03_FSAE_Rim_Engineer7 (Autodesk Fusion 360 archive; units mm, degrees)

design "03 FSAE Rim - Engineer 7" references "Hexagon Socket Head Cap Screw DIN 912 - M4 x 0.7 x 16 Steel 4.6 Plain", "Hexagon Nut DIN 934 - M4 x 0.7 Steel 6 Plain"
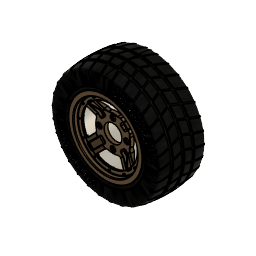
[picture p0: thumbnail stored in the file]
part number: 2026-07-27-09-56-27-671
part number: 2026-08-04-10-59-52-273
part number: 2026-08-04-10-59-52-284
part number: 2026-08-04-10-59-52-289
sketch "Sketch1" plane through (0, 0, 0) normal (1, 0, 0) x axis (0, 1, 0)
  line L1 (153.5, 0) -> (0, 0)
  line L2 (0, 119.5) -> (0, 104)
  line L3 (143.5, 124.5) -> (5, 124.5)
  line L4 (148.5, 134.75) -> (148.5, 129.5)
  line L5 (153.5, 138.25) -> (152, 138.25)
  line L6 (2.5, 119.5) -> (2.5, 104)
  line L7 (143.5, 122) -> (5, 122)
  line L8 (151, 134.75) -> (151, 129.5)
  line L9 (153.5, 135.75) -> (152, 135.75)
  line L10 (2.5, 104) -> (0, 104)
  line L11 (153.5, 135.75) -> (153.5, 138.25)
  arc A1 centre (152, 134.75) radius 3.5 clockwise from (148.5, 134.75) to (152, 138.25)
  arc A2 centre (143.5, 129.5) radius 5 clockwise from (148.5, 129.5) to (143.5, 124.5)
  arc A3 centre (5, 119.5) radius 5 clockwise from (0, 119.5) to (5, 124.5)
  arc A4 centre (5, 119.5) radius 2.5 clockwise from (2.5, 119.5) to (5, 122)
  arc A5 centre (143.5, 129.5) radius 7.5 clockwise from (151, 129.5) to (143.5, 122)
  arc A6 centre (152, 134.75) radius 1 clockwise from (151, 134.75) to (152, 135.75)
  point P1 (0, 0)
  point P2 (0, 0)
  point P4 (0, 104)
  point P3 (153.5, 0)
  point P7 (153.5, 138.25)
  point P6 (148.5, 124.5)
  point P5 (0, 124.5)
  coincident P1 P2
  horizontal L1
  perpendicular L1 L2
  perpendicular L2 L3
  perpendicular L3 L4
  perpendicular L4 L5
  vertical P1 P4
  vertical P3 P7
  tangent L4 A1
  tangent L5 A1
  coincident P6 L3
  coincident P6 L4
  tangent L3 A2
  tangent L4 A2
  coincident P5 L2
  coincident P5 L3
  tangent L2 A3
  tangent L3 A3
  equal A2 A3
  perpendicular L6 L10
  perpendicular L9 L11
  dimension "d1" distance P2 P3 = 153.5
  dimension "d2" = 208
  dimension "d3" = 249
  dimension "d4" = 276.5
  dimension "d5" distance P5 P6 = 148.5
  dimension "d6" radius A1 = 3.5
  dimension "d7" radius A2 = 5
  dimension "d8" = 2.5
revolve "Revolve1" sketch "Sketch1" AlongAngle 360 bodies "FSAE Rim Back"
sketch "Sketch2" plane through (0, 0, 0) normal (0, -1, 0) x axis (1, 0, 0)
  circle C1 centre (0, 0) radius 104
  circle C2 centre (0, 0) radius 119.5
  circle C3 centre (0, 0) radius 112
  circle C4 centre (0, 112) radius 2.15
  point P1 (0, 0)
  point P3 (0, 0)
  point P4 (0, 112)
  coincident P1 P3
  coincident C3 P4
  vertical P3 P4
  dimension "d10" diameter C3 = 224
  dimension "d11" diameter C4 = 4.3
extrude "Extrude1" cut sketch "Sketch2" profile of C4 to an object
circular_pattern "C-Pattern1" TotalAngle 360
canvas "Canvas1"
move "Move1"
sketch "Sketch4" plane through (0, 0, 0) normal (1, 0, 0) x axis (0, 1, 0)
  line L1 (14, 0) -> (0, 0)
  line L2 (14, 72.5) -> (14, 0)
  line L3 (-8, 102.5) -> (14, 72.5)
  line L4 (-8, 124.5) -> (-8, 102.5)
  line L5 (-23.5, 124.5) -> (-8, 124.5)
  line L6 (-23.5, 138) -> (-23.5, 124.5)
  line L7 (-28.25, 138) -> (-23.5, 138)
  line L8 (-28.25, 0) -> (-28.25, 138)
  line L9 (0, 0) -> (-28.25, 0)
  line L10 (-13, 118.1658) -> (-28.25, 119.5)
  line L11 (-13, 102.5) -> (-13, 118.1658)
  line L12 (0, 68.6338) -> (-13, 102.5)
  line L13 (0, 0) -> (0, 68.6338)
  point P1 (0, 0)
  point P2 (0, 0)
  point P11 (0, 0)
  point P12 (-28.25, 119.5)
  point P5 (-8, 102.5)
  point P14 (-13, 102.5)
  point P3 (14, 0)
  point P4 (14, 72.5)
  point P6 (-8, 124.5)
  point P8 (-23.5, 138)
  point P9 (-28.25, 138)
  coincident P1 P2
  horizontal L1
  perpendicular L1 L2
  perpendicular L1 L4
  perpendicular L4 L5
  perpendicular L5 L6
  perpendicular L6 L7
  coincident P1 P11
  collinear L1 L9
  perpendicular L8 L9
  coincident L8 P12
  parallel L8 L11
  vertical L13
  horizontal P5 P14
  dimension "d29" distance P2 P3 = 14
  dimension "d30" = 145
  dimension "d31" = 205
  dimension "d32" = 249
  dimension "d33" = 276
  dimension "d34" distance P4 P6 = 22
  dimension "d35" distance P6 P8 = 15.5
  dimension "d36" distance P8 P9 = 4.75
  dimension "d37" distance L4 L11 = 5
  dimension "d38" angle L12 L13 = 159
  dimension "d39" angle L10 L11 = 95
  dimension "d40" = 239
revolve "Revolve3" sketch "Sketch4" AlongAngle 360 bodies "FSAE Rim Front"
sketch "Sketch5" plane through (0, 0, 0) normal (0, -1, 0) x axis (1, 0, 0)
  circle C1 centre (0, 0) radius 68.6338
  circle C2 centre (0, 0) radius 33
  point P1 (0, 0)
  point P3 (0, 0)
  coincident P1 P3
  dimension "d42" diameter C2 = 66
extrude "Extrude2" cut sketch "Sketch5" profile of C2 to an object
sketch "Sketch6" plane through (0, 0, 0) normal (0, -1, 0) x axis (1, 0, 0)
  circle C1 centre (0, 0) radius 33
  circle C2 centre (0, 0) radius 68.6338
  circle C3 centre (0, 0) radius 50.8
  point P1 (0, 0)
  point P4 (0, 0)
  point P3 (0, 50.8)
  coincident P1 P4
  coincident P3 C3
  vertical P1 P3
  dimension "d45" diameter C3 = 101.6
hole "Hole1" HoleDiameter 10.5 TipAngle 180 CBDepth 5 CBDiameter 20
chamfer "Chamfer2" sketch "Sketch1" distance 0.5
circular_pattern "C-Pattern2" TotalAngle 360
sketch "Sketch7" plane through (0, -13, 0) normal (0, -1, 0) x axis (1, 0, 0)
  circle C1 centre (0, 0) radius 102.5
  circle C2 centre (0, 0) radius 118.1658
  circle C3 centre (0, 0) radius 112
  point P1 (0, 0)
  point P3 (0, 0)
  point P4 (0, 112)
  coincident P1 P3
  coincident C3 P4
  vertical P1 P4
  dimension "d53" diameter C3 = 224
hole "Hole2" HoleDiameter 4.3 TipAngle 180
circular_pattern "C-Pattern3" TotalAngle 360
fillet "Fillet1" radius 1 3 2
chamfer "Chamfer1" distance 0.5
form "Form1" bodies "Tire"
fillet "Fillet2" radius 5
sketch "Sketch8" plane through (0, 0, 0) normal (1, 0, 0) x axis (0, 1, 0)
  line L1 (47.5, 224.911) -> (47.5, 204.911)
  line L2 (57.5, 224.911) -> (47.5, 224.911)
  line L3 (57.5, 204.9943) -> (57.5, 224.911)
  line L4 (87.5, 224.911) -> (87.5, 204.2438)
  line L5 (97.5, 224.911) -> (87.5, 224.911)
  line L6 (97.5, 203.6595) -> (97.5, 224.911)
  line L7 (17.5, 224.911) -> (17.5, 203.6595)
  line L8 (7.5, 224.911) -> (17.5, 224.911)
  line L9 (7.5, 202.9073) -> (7.5, 224.911)
  arc A1 centre (57.5, -395.0057) radius 600 clockwise from (-46, 196) to (161, 196)
  point P2 (-46, 196)
  point P3 (161, 196)
  point P8 (57.5, 204.9943)
  point P9 (87.5, 204.2438)
  point P12 (97.5, 203.6595)
  point P13 (17.5, 203.6595)
  point P16 (7.5, 202.9073)
  point P5 (47.5, 204.911)
  point P1 (0, 0)
  point P6 (47.5, 224.911)
  point P7 (57.5, 224.911)
  horizontal P2 P3
  vertical L1
  perpendicular L1 L2
  midpoint A1 P8
  perpendicular L2 L3
  coincident A1 P9
  parallel L3 L4
  perpendicular L4 L5
  coincident A1 P12
  perpendicular L5 L6
  coincident A1 P13
  perpendicular L5 L7
  perpendicular L7 L8
  coincident A1 P16
  perpendicular L8 L9
  collinear L2 L8
  collinear L2 L5
  equal L2 L8
  equal L2 L5
  coincident A1 P5
  dimension "d68" radius A1 = 600
  dimension "d69" distance P1 P3 = 196
  dimension "d70" distance P1 P2 = 46
  dimension "d71" distance P1 P3 = 161
  dimension "d73" distance P6 P7 = 10
  dimension "d74" distance L1 L7 = 30
  dimension "d75" distance L3 L4 = 30
  dimension "d76" distance P5 P6 = 20
revolve "Revolve4" AlongAngle 360
revolve "Revolve5" sketch "Sketch8" AlongAngle 360
work_plane "WorkPlane1" AlongDistance 275 ExtraOffset 0
sketch "Sketch9" plane through (0, 0, 275) normal (0, 0, 1) x axis (1, 0, 0)
  line L1 (-48.7008, 53.5011) -> (0, -75.7953)
  line L2 (0, 197.5142) -> (-48.7008, 53.5011)
  line L3 (-43.392, 53.5917) -> (4.6791, -74.0329)
  line L4 (4.7365, 195.9124) -> (-43.392, 53.5917)
  line L5 (4.6791, -74.0329) -> (0, -75.7953)
  line L6 (0, 197.5142) -> (4.7365, 195.9124)
  perpendicular L3 L5
  perpendicular L2 L6
  dimension "d80" = 5
step "SurfaceExtend" extendDistance 125
extrude "Extrude3" cut sketch "Sketch9" to an object
circular_pattern "C-Pattern4" countU 30 TotalAngle 360
remove_body "RemoveBody1"
remove_body "RemoveBody2"
work_plane "WorkPlane2" AlongDistance -150 ExtraOffset 0
sketch "Sketch10" plane through (0, -150, 0) normal (0, 1, 0) x axis (1, 0, 0)
  circle C1 centre (0, 0) radius 157.5
  point P1 (0, 0)
  point P2 (0, 0)
  coincident P1 P2
  dimension "d88" diameter C1 = 315
  dimension "d89" Text1-Height = 20
extrude "Extrude4" sketch "Sketch10" blind 2
circular_pattern "C-Pattern5" TotalAngle 360
component_from_bodies "Body->Comp1"
component_from_bodies "Body->Comp2"
component_from_bodies "Body->Comp3"
sketch "Sketch1" plane through (0, -13, 0) normal (0, -1, 0) x axis (1, 0, 0)
  line L1 (0, 103.056) -> (0, 0)
  line L2 (103.056, 0) -> (0, 0)
  line L3 (72.8716, 72.8716) -> (0, 0)
  line L4 (88.3726, 53.0172) -> (60.1041, 24.7487)
  line L5 (53.0172, 88.3726) -> (24.7487, 60.1041)
  circle C1 centre (0, 0) radius 103.056
  circle C2 centre (0, 112) radius 2.15
  circle C3 centre (56, 96.9948) radius 2.15
  circle C4 centre (96.9948, 56) radius 2.15
  circle C5 centre (112, 0) radius 2.15
  circle C6 centre (96.9948, -56) radius 2.15
  circle C7 centre (56, -96.9948) radius 2.15
  circle C8 centre (0, -112) radius 2.15
  circle C9 centre (-56, -96.9948) radius 2.15
  circle C10 centre (-96.9948, -56) radius 2.15
  circle C11 centre (-112, 0) radius 2.15
  circle C12 centre (-96.9948, 56) radius 2.15
  circle C13 centre (-56, 96.9948) radius 2.15
  circle C14 centre (0, 0) radius 116.3331
  arc A1 centre (0, 0) radius 65 clockwise from (0, 65) to (65, 0)
  arc A2 centre (0, 0) radius 65 clockwise from (65, 0) to (0, 65)
  point P2 (0, 0)
  point P16 (0, 0)
  point P17 (0, 103.056)
  point P18 (103.056, 0)
  point P15 (0, 0)
  point P19 (0, 0)
  point P20 (72.8716, 72.8716)
  point P22 (24.7487, 60.1041)
  point P21 (60.1041, 24.7487)
  point P23 (53.0172, 88.3726)
  point P24 (88.3726, 53.0172)
  point P25 (0, 65)
  point P26 (65, 0)
  concentric C1 A1
  coincident P2 P16
  coincident C1 P17
  vertical L1
  coincident C1 P18
  perpendicular L1 L2
  coincident P15 P19
  coincident C1 P20
  coincident P22 A1
  coincident P21 A1
  coincident C1 P23
  coincident C1 P24
  coincident L1 P25
  coincident L2 P26
  concentric A1 A2
  dimension "d95" diameter A1 = 130
  dimension "d96" angle L1 L3 = 45
extrude "Extrude1" cut sketch "Sketch1" profile of C1 L1 L2 L4 L5 A1 to an object
circular_pattern "C-Pattern1" TotalAngle 360
sketch "Sketch2" plane through (0, -13, 0) normal (0, -1, 0) x axis (1, 0, 0)
  line L1 (72.8716, 72.8716) -> (0, 0)
  line L2 (65.9862, 82.9568) -> (25.8367, 42.8073)
  line L3 (82.9568, 65.9862) -> (42.8073, 25.8367)
  arc A1 centre (0, 0) radius 103.056 clockwise from (-53.0172, 88.3726) to (53.0172, 88.3726)
  arc A2 centre (0, 0) radius 103.056 clockwise from (53.0172, 88.3726) to (88.3726, 53.0172)
  arc A3 centre (0, 0) radius 103.056 clockwise from (88.3726, 53.0172) to (88.3726, -53.0172)
  arc A4 centre (0, 0) radius 103.056 clockwise from (88.3726, -53.0172) to (53.0172, -88.3726)
  arc A5 centre (0, 0) radius 103.056 clockwise from (53.0172, -88.3726) to (-53.0172, -88.3726)
  arc A6 centre (0, 0) radius 103.056 clockwise from (-53.0172, -88.3726) to (-88.3726, -53.0172)
  arc A7 centre (0, 0) radius 103.056 clockwise from (-88.3726, -53.0172) to (-88.3726, 53.0172)
  arc A8 centre (0, 0) radius 103.056 clockwise from (-88.3726, 53.0172) to (-53.0172, 88.3726)
  circle C1 centre (0, 112) radius 2.15
  circle C2 centre (56, 96.9948) radius 2.15
  circle C3 centre (96.9948, 56) radius 2.15
  circle C4 centre (112, 0) radius 2.15
  circle C5 centre (96.9948, -56) radius 2.15
  circle C6 centre (56, -96.9948) radius 2.15
  circle C7 centre (0, -112) radius 2.15
  circle C8 centre (-56, -96.9948) radius 2.15
  circle C9 centre (-96.9948, -56) radius 2.15
  circle C10 centre (-112, 0) radius 2.15
  circle C11 centre (-96.9948, 56) radius 2.15
  circle C12 centre (-56, 96.9948) radius 2.15
  circle C13 centre (0, 0) radius 116.3331
  circle C14 centre (0, 0) radius 50
  circle C15 centre (0, 0) radius 106
  point P23 (0, 0)
  point P25 (0, 0)
  point P27 (25.8367, 42.8073)
  point P28 (42.8073, 25.8367)
  point P29 (82.9568, 65.9862)
  point P30 (65.9862, 82.9568)
  parallel L1 L2
  parallel L1 L3
  coincident P23 P25
  concentric C14 C15
  coincident C14 P27
  coincident C14 P28
  coincident C15 P29
  coincident C15 P30
  dimension "d103" distance L1 L2 = 12
  dimension "d104" distance L1 L3 = 12 (= "d103")
  dimension "d105" diameter C14 = 100
  dimension "d106" diameter C15 = 212
extrude "Extrude2" cut sketch "Sketch2" profile of A2 L2 L3 C14 C15 to an object offset 2
fillet "Fillet1" radius 5
fillet "Fillet2" radius 10
fillet "Fillet3" radius 2
circular_pattern "C-Pattern2" TotalAngle 360
fillet "Fillet4" radius 15 5
chamfer "Chamfer1" sketch "Sketch1" distance 1
step "Screw1"
joint "Assemble" alignAngle 0 alignOffsetX 0 alignOffsetY 0 alignOffsetZ 0
step "Screw2"
joint "Assemble" alignAngle 0 alignOffsetX 0 alignOffsetY 0 alignOffsetZ 0
step "Screw3"
joint "Assemble" alignAngle 0 alignOffsetX 0 alignOffsetY 0 alignOffsetZ 0
step "Screw4"
joint "Assemble" alignAngle 0 alignOffsetX 0 alignOffsetY 0 alignOffsetZ 0
step "Screw5"
joint "Assemble" alignAngle 0 alignOffsetX 0 alignOffsetY 0 alignOffsetZ 0
step "Screw6"
joint "Assemble" alignAngle 0 alignOffsetX 0 alignOffsetY 0 alignOffsetZ 0
step "Screw7"
joint "Assemble" alignAngle 0 alignOffsetX 0 alignOffsetY 0 alignOffsetZ 0
step "Screw8"
joint "Assemble" alignAngle 0 alignOffsetX 0 alignOffsetY 0 alignOffsetZ 0
step "Screw9"
joint "Assemble" alignAngle 0 alignOffsetX 0 alignOffsetY 0 alignOffsetZ 0
step "Screw10"
joint "Assemble" alignAngle 0 alignOffsetX 0 alignOffsetY 0 alignOffsetZ 0
step "Screw11"
joint "Assemble" alignAngle 0 alignOffsetX 0 alignOffsetY 0 alignOffsetZ 0
step "Screw12"
joint "Assemble" alignAngle 0 alignOffsetX 0 alignOffsetY 0 alignOffsetZ 0
step "Nut13"
joint "Assemble" alignAngle 0 alignOffsetX 0 alignOffsetY 0 alignOffsetZ 0
step "Nut14"
joint "Assemble" alignAngle 0 alignOffsetX 0 alignOffsetY 0 alignOffsetZ 0
step "Nut15"
joint "Assemble" alignAngle 0 alignOffsetX 0 alignOffsetY 0 alignOffsetZ 0
step "Nut16"
joint "Assemble" alignAngle 0 alignOffsetX 0 alignOffsetY 0 alignOffsetZ 0
step "Nut17"
joint "Assemble" alignAngle 0 alignOffsetX 0 alignOffsetY 0 alignOffsetZ 0
step "Nut18"
joint "Assemble" alignAngle 0 alignOffsetX 0 alignOffsetY 0 alignOffsetZ 0
step "Nut19"
joint "Assemble" alignAngle 0 alignOffsetX 0 alignOffsetY 0 alignOffsetZ 0
step "Nut20"
joint "Assemble" alignAngle 0 alignOffsetX 0 alignOffsetY 0 alignOffsetZ 0
step "Nut21"
joint "Assemble" alignAngle 0 alignOffsetX 0 alignOffsetY 0 alignOffsetZ 0
step "Nut22"
joint "Assemble" alignAngle 0 alignOffsetX 0 alignOffsetY 0 alignOffsetZ 0
step "Nut23"
joint "Assemble" alignAngle 0 alignOffsetX 0 alignOffsetY 0 alignOffsetZ 0
step "Nut24"
joint "Assemble" alignAngle 0 alignOffsetX 0 alignOffsetY 0 alignOffsetZ 0
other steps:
base_feature "Base Feature1" bodies "FSAE Rim Back"
base_feature "Base Feature1" bodies "Tire"
base_feature "Base Feature1" bodies "FSAE Rim Front"
create_component "CreateComponent1"
reparent_decal "ReparentDecal1"
remove_body "RemoveBody3"
create_component "CreateComponent2"
reparent_decal "ReparentDecal2"
remove_body "RemoveBody4"
create_component "CreateComponent3"
reparent_decal "ReparentDecal3"
remove_body "RemoveBody5"
joint_origin "JointOrigin1"
joint_origin "JointOrigin2"
joint_origin "JointOrigin3"
joint_origin "JointOrigin4"
joint_origin "JointOrigin5"
joint_origin "JointOrigin6"
joint_origin "JointOrigin7"
joint_origin "JointOrigin8"
joint_origin "JointOrigin9"
joint_origin "JointOrigin10"
joint_origin "JointOrigin11"
joint_origin "JointOrigin12"
joint_origin "JointOrigin1"
joint_origin "JointOrigin2"
joint_origin "JointOrigin3"
joint_origin "JointOrigin4"
joint_origin "JointOrigin5"
joint_origin "JointOrigin6"
joint_origin "JointOrigin7"
joint_origin "JointOrigin8"
joint_origin "JointOrigin9"
joint_origin "JointOrigin10"
joint_origin "JointOrigin11"
joint_origin "JointOrigin12"
named bodies: "FSAE Rim Back", "FSAE Rim Front", "Tire"

design "Hexagon Nut DIN 934 - M4 x 0.7 Steel 6 Plain"
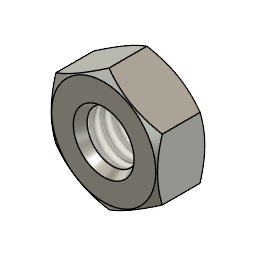
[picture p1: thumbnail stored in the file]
description: Hexagon Nut DIN 934 - M4 x 0.7
part number: DIN 934 - M4 x 0.7 Steel 6 Plain
parameter "adsk_nheig" = 3.2
parameter "adsk_maxdia" = 8.085
parameter "adsk_nomdia" = 4
parameter "adsk_waflat" = 7
parameter "adsk_chamang1" = 30
parameter "adsk_chamang2" = 30
parameter "adsk_beardia" = 6.86 (= "adsk_waflat * 0.98")
sketch "Sketch1" plane through (0, 0, 0) normal (0, 1, 0) x axis (1, 0, 0)
  line L1 (0, -3.2) -> (0, 0)
  line L2 (-3.43, 0) -> (-2, 0)
  line L3 (-4.0425, -0.3536) -> (-3.43, 0)
  line L4 (-4.0425, -2.8464) -> (-4.0425, -0.3536)
  line L5 (-3.43, -3.2) -> (-4.0425, -2.8464)
  line L6 (-2, -3.2) -> (-3.43, -3.2)
  line L7 (-2, 0) -> (-2, -3.2)
  point P3 (0, -3.2)
  point P1 (0, 0)
  point P2 (0, 0)
  point P10 (0, 0)
  point P5 (-3.43, 0)
  point P8 (-3.43, -3.2)
  vertical L1
  coincident L1 P3
  coincident P1 L1
  horizontal L2
  coincident P1 L2
  coincident P2 P10
  coincident P3 L6
  vertical P5 P8
  dimension "d121" = 4 (= "adsk_nomdia")
  dimension "d122" angle L2 L3 = 30 (= "adsk_chamang1")
  dimension "d123" angle L5 L6 = 30 (= "adsk_chamang2")
  dimension "d128" = 8.085 (= "adsk_maxdia")
  dimension "d172" = 6.86 (= "adsk_beardia")
  dimension "d179" distance L2 L6 = 3.2 (= "adsk_nheig")
revolve "Revolve1" sketch "Sketch1" AlongAngle 360
sketch "Sketch8" plane through (0, 0, 3.2) normal (0, 0, 1) x axis (1, 0, 0)
  line L1 (-3.5, 2.0228) -> (-3.5, -2.0228)
  circle C1 centre (0, 0) radius 2
  circle C2 centre (0, 0) radius 4.0425
  point P3 (-3.5, 2.0228)
  point P2 (-3.5, -2.0228)
  point P1 (0, 0)
  coincident P3 C2
  coincident P2 C2
  vertical L1
  dimension "d114" distance P1 L1 = 3.5 (= "adsk_waflat / 2")
extrude "Extrude5" cut sketch "Sketch8" profile of L1 C2 no distance stored
circular_pattern "C-Pattern2" TotalAngle 360
thread "Thread3" ThreadOffset 0 ThreadLength 10
sketch "Sketch12" plane through (0, 0, 0) normal (0, 1, 0) x axis (1, 0, 0)
  line L1 (0, 0) -> (-2, 0)
  line L2 (-2, 0) -> (-1.0762, -1.6)
  line L3 (0, -3.2) -> (-2, -3.2)
  line L4 (-2, -3.2) -> (-1.0762, -1.6)
  line L5 (0, -3.2) -> (0, 0)
  point P4 (-1.0762, -1.6)
  point P7 (-1.0762, -1.6)
  point P2 (-2, 0)
  point P5 (-2, -3.2)
  point P6 (0, -3.2)
  point P9 (0, -3.2)
  point P1 (0, 0)
  point P3 (0, 0)
  horizontal L1
  coincident P4 P7
  vertical P2 P5
  coincident P6 P9
  coincident P1 P3
  perpendicular L3 L5
  dimension "d169" angle L3 L4 = 60
  dimension "d177" distance P2 L5 = 2 (= "adsk_nomdia * 0.5")
  dimension "d178" angle L1 L2 = 60
revolve "Revolve3" sketch "Sketch12" AlongAngle 360
joint_origin "JointOrigin9" OffsetX 0 OffsetY 0 OffsetZ 0 AngleZ 0
joint_origin "JointOrigin10" OffsetX 0 OffsetY 0 OffsetZ 3.2 (= "adsk_nheig") AngleZ 0

design "Hexagon Socket Head Cap Screw DIN 912 - M4 x 0.7 x 16 Steel 4.6 Plain"
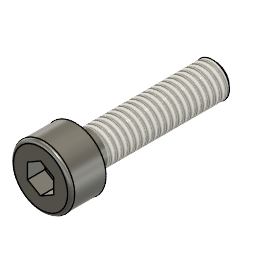
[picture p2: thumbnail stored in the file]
description: Hexagon Socket Head Cap Screw DIN 912 - M4 x 0.7 x 16
part number: DIN 912 - M4 x 0.7 x 16 Steel 4.6 Plain
parameter "adsk_nomlen" = 16
parameter "adsk_headh" = 4
parameter "adsk_headdia" = 7
parameter "adsk_nomdia" = 4
parameter "adsk_philwidth" = 3
parameter "adsk_phildepth" = 2
parameter "adsk_thrlen" = 14.25
parameter "adsk_startlen" = 0.4294
parameter "adsk_endpointdia" = 3.1412
sketch "Sketch1" plane through (0, 0, 0) normal (0, 1, 0) x axis (1, 0, 0)
  line L1 (-2, 16) -> (-2, 0)
  line L2 (0, 16) -> (-2, 16)
  line L3 (0, -4) -> (0, 16)
  line L4 (-3.5, 0) -> (-2, 0)
  line L5 (-3.5, -4) -> (-3.5, 0)
  line L6 (0, -4) -> (-3.5, -4)
  point P1 (0, 0)
  point P4 (0, 16)
  point P7 (0, -4)
  point P5 (-3.5, 0)
  perpendicular L1 L2
  collinear P1 P4 P7
  perpendicular L1 L4
  coincident P1 L4
  vertical L3
  coincident L3 P7
  perpendicular L3 L6
  dimension "d101" distance P1 L2 = 16 (= "adsk_nomlen")
  dimension "d102" distance P5 L6 = 4 (= "adsk_headh")
  dimension "d109" = 7 (= "adsk_headdia")
  dimension "d110" = 4 (= "adsk_nomdia")
revolve "Revolve1" sketch "Sketch1" AlongAngle 360
work_plane "WorkPlane1" AlongDistance 4 (= "adsk_headh")
sketch "Sketch6" plane through (0, 0, 4) normal (0, 0, 1) x axis (1, 0, 0)
  line L1 (1.5, -0.866) -> (0, -1.7321)
  line L2 (1.5, 0.866) -> (1.5, -0.866)
  line L3 (0, 1.7321) -> (1.5, 0.866)
  line L4 (-1.5, 0.866) -> (0, 1.7321)
  line L5 (-1.5, -0.866) -> (-1.5, 0.866)
  line L6 (0, -1.7321) -> (-1.5, -0.866)
  point P1 (0, 0)
  point P8 (0, 0)
  coincident P1 P8
  vertical L2
  dimension "d111" distance L2 L5 = 3 (= "adsk_philwidth")
extrude "Extrude1" cut sketch "Sketch6" no distance stored
extrude "Extrude2" cut of existing geometry no distance stored taper -85
thread "Thread3" ThreadOffset 0 ThreadLength 14.25 (= "min(adsk_thrlen; adsk_nomlen - 0.001 mm)")
fillet "Fillet4" radius 0.4 (= "adsk_nomdia * 0.1")
sketch "Sketch7" plane through (0, 0, 0) normal (0, 1, 0) x axis (1, 0, 0)
  line L1 (-2.04, 15.5706) -> (-2.04, 16)
  line L2 (-1.5706, 16) -> (-2.04, 15.5706)
  line L3 (0, -4) -> (0, 16)
  line L4 (0, 16) -> (-2.04, 16)
  point P5 (0, 16)
  point P7 (0, 16)
  point P4 (-1.5706, 16)
  point P3 (-2.04, 15.5706)
  coincident P5 P7
  perpendicular L3 L4
  coincident P4 L4
  perpendicular L1 L4
  dimension "d104" distance P4 L3 = 1.5706 (= "adsk_endpointdia / 2")
  dimension "d105" distance L1 P7 = 2.04 (= "adsk_nomdia * 0.51")
  dimension "d106" distance P3 L4 = 0.4294 (= "adsk_startlen")
revolve "Revolve3" sketch "Sketch7" AlongAngle 360
joint_origin "JointOrigin2" OffsetX 0 OffsetY 0 OffsetZ 0 AngleZ 0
